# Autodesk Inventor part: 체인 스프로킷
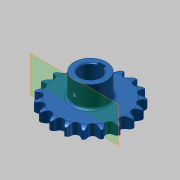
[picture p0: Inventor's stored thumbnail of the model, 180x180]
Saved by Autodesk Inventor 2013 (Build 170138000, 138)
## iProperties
Created: 2014-11
Part Number: 체인 스프로킷
Material: Steel
Document SubType Name: Modeling
Designer: KYOUNG IL JANG
Density: 7.85 g/cm^3
Mass: 738.264 g
Surface Area: 236.923 cm^2
Volume: 94.0463 cm^3
CustomPartVersion: 1
Company: 한국ATC센터
Author: KYOUNG IL JANG
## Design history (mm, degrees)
sketch "이론적 톱니 프로파일"
  geometry: L1 (0, 0)-(0, 45.567); L2 (0, 0)-(14.795, 43.098); L3 (0, 45.567)-(14.795, 43.098); L4 (0, 45.567)-(5.661, 50.015); L5 (5.661, 50.015)-(-5.141, 45.406); L6 (-12.428, 43.493)-(-5.573, 46.417); L7 (-5.141, 45.406)-(-5.573, 46.417); L8 (5.573, 46.417)-(5.141, 45.406); L9 (0, 0)-(8.138, 48.771); A1 r 45.567 centre (0, 0) between (0, 45.567) and (14.795, 43.098); A2 r 49.445 centre (0, 0) between (7.302, 48.903) and (-7.302, 48.903); A3 r 4.545 centre (0, 45.567) between (-3.574, 42.758) and (3.574, 42.758); A4 r 7.453 centre (12.428, 43.493) between (7.302, 48.903) and (5.573, 46.417); A5 r 7.453 centre (-12.428, 43.493) between (-5.573, 46.417) and (-7.302, 48.903); A6 r 11.745 centre (5.661, 50.015) between (-5.141, 45.406) and (-3.574, 42.758); A7 r 11.745 centre (-5.661, 50.015) between (3.574, 42.758) and (5.141, 45.406); 2 further points
  constraints: 18 end point, 15 point on circle, 7 centre point, 3 coincident, 3 point on line, 3 symmetric about line, 3 tangent, 1 equal radius, 1 midpoint, 1 parallel, 1 vertical, 1 other
  dimensions: "d0" = 91.13301 diameter of A1 (computed from da_p, da_z); "d2" = 18.9474 deg angle of L2 L1 (computed from da_z); "d3" = 4.545 radius of A3 (= 0.5 x da_Dr + da_SC); "d10" = 128.158 deg angle of L4 L1 (computed from da_z); "d11" = 15.0526 deg angle of L5 L4 (computed from da_z); "d12" = 7.2 distance of L3.start L4.end (= 0.8 x da_Dr); "d13" = 11.745 distance of L4.end L5.end (= 1.3 x da_Dr + da_SC); "d14" = 12.6 distance of A4.centre L1.end (= 1.4 x da_Dr); "d23" = 4.5 distance from line of L9.end L3 (= da_Ha)
sketch "톱니 프로파일"
  geometry: L1 (0, 0)-(0, 45.567); L2 (0, 45.567)-(4.203, 43.837); L3 (0, 45.567)-(-4.203, 43.837); A1 r 4.545 centre (0, 45.567) between (-4.203, 43.837) and (4.203, 43.837); A2 r 22.68 centre (25.176, 35.206) between (7.12, 48.93) and (4.203, 43.837); A3 r 22.68 centre (-25.176, 35.206) between (-4.203, 43.837) and (-7.12, 48.93); A4 r 49.445 centre (0, 0) between (-7.12, 48.93) and (7.12, 48.93) reference; 1 further point
  constraints: 9 point on circle, 6 end point, 3 centre point, 2 tangent, 1 coincident, 1 equal radius, 1 vertical, 1 other
  dimensions: "d44" = 135.263 deg angle of L3 L2 (= da_Alfa); "d45" = 22.68 radius of A2 (= da_Re); "d46" = 4.545 radius of A1 (= da_Ri)
sketch "단면 프로파일"
  geometry: L1 (49.445, 0)-(-49.445, 0) reference; L2 (33.265, 6.65)-(-33.265, 6.65); L3 (-33.265, 6.65)-(-33.265, -6.65); L4 (-33.265, -6.65)-(33.265, -6.65); L5 (33.265, -6.65)-(33.265, 6.65); L6 (33.265, 6.65)-(49.445, 6.65); L7 (49.445, 6.65)-(49.445, -6.65); L8 (49.445, -6.65)-(33.265, -6.65); L9 (33.265, -6.65)-(33.265, 6.65); L10 (42.183, 6.65)-(0, 6.65); L11 (0, 6.65)-(0, -6.65); L12 (0, -6.65)-(42.183, -6.65); L13 (0, 6.65)-(0, -6.65); L14 (49.445, 4.775)-(49.445, -4.775); A1 r 15 centre (42.183, -8.35) between (49.445, 4.775) and (42.183, 6.65); A2 r 15 centre (42.183, 8.35) between (42.183, -6.65) and (49.445, -4.775); 2 further points
  constraints: 26 end point, 7 midpoint, 5 perpendicular, 4 parallel, 4 point on circle, 3 point on line, 3 symmetric about line, 2 centre point, 2 horizontal, 2 tangent, 1 collinear, 1 other
  dimensions: "d30" = 13.3 distance between parallel lines of L8 L6 (= da_Bf); "d31" = 66.53007 distance between parallel lines of L3 L5 (= da_Ds); "d32" = 13.3 distance between parallel lines of L4 L2 (= da_Bs); "d33" = 1.875 distance from line of L14.start L6 (= da_Ba); "d34" = 15 radius of A1 (= da_Rx); "d43" = 6.65 distance between parallel lines of L4 L1 (computed from da_k, da_pt, da_Bs)
revolve "슈라우드" stored, may be unused: angle "d36" = 90 deg
revolve "스트랜드" stored, may be unused: angle "d37" = 90 deg
extrude "이론적 톱니" cut sketch "이론적 톱니 프로파일" stored distance "d18" = 10; taper "d19" = 0 deg; dims "d49" = 0, "form_type" = 0 [user parameter]
extrude "톱니" cut sketch "톱니 프로파일" stored distance "d47" = 10; taper "d48" = 0 deg; dims "d50" = 10, "form_type" = 0 [user parameter]
node "타이밍 평면"
node "작업 평면3"
sketch "스케치5"
  geometry: C1 r 20 at (0, -45.567); 1 further point
  constraints: 1 centre point, 1 coincident
  dimensions: "d52" = 40 diameter of C1
extrude "돌출4" join sketch "스케치5" stored distance "d53" = 10; taper "d54" = 0 deg
sketch "스케치6"
  geometry: L1 (4, 11.843)-(4, 16.5); L2 (4, 16.5)-(-4, 16.5); L3 (-4, 16.5)-(-4, 11.843); A1 r 12.5 centre (0, 0) between (4, 11.843) and (-4, 11.843); 1 further point
  constraints: 6 end point, 2 parallel, 2 point on circle, 1 centre point, 1 coincident, 1 perpendicular, 1 vertical
  dimensions: "d55" = 25 diameter of A1; "d56" = 29 dimension on A1 L2 (computed from d55); "d57" = 8 distance of L1.end L2.end
extrude "돌출5" cut sketch "스케치6" stored distance "d58" = 10; taper "d59" = 0 deg
fillet "모깎기2" dims "d60" = 3
chamfer "모따기1" distance "d61" = 1; stored, may be unused: second distance "d62" = 2, angle "d63" = 45 deg
node "작업 평면4"
sketch "스케치7"
  geometry: L1 (-13.5, -13.3)-(13.5, -13.3) reference; 4 further points
  constraints: 1 vertical alignment
  dimensions: "d65" = 25 distance from line of point (0, 11.7) L1
hole "구멍1" sketch "스케치7" diameter "d66" = 5; stored, may be unused: countersink angle "d70" = 90 deg, drill point angle "d72" = 118 deg; dims "d67" = 6, "d68" = 4, "d69" = 2, "d71" = 8
feature "스레드1" dims "d73" = 10, "d74" = 0
body "Solid1"
pattern_linear "스트랜드 패턴" dims "d40" = 24 (= da_pt)
pattern_circular "톱니 패턴" dims angle "d21" = 360 deg
other parameters: "da_p" = 15 [user parameter; used in 1 equation term], "da_Dr" = 9 [user parameter; used in 4 equation terms], "da_SC" = 0.045 [user parameter; used in 2 equation terms], "da_Ha" = 4.5 [user parameter; used in 1 equation term], "da_pt" = 24 [user parameter; used in 2 equation terms], "da_Bf" = 13.3 [user parameter; used in 1 equation term], "d28" = 0, "d29" = 0, "da_Ba" = 1.875 [user parameter; used in 1 equation term], "da_Rx" = 15 [user parameter; used in 1 equation term], "da_Ra" = 0.6 [user parameter], "da_Bs" = 13.3 [user parameter; used in 2 equation terms], "da_Ds" = 66.53007 [user parameter; used in 1 equation term], "d42" = 0, "da_Re" = 22.68 [user parameter; used in 1 equation term], "da_Ri" = 4.545 [user parameter; used in 1 equation term], "da_Alfa" = 135.263 deg [user parameter; used in 1 equation term]
